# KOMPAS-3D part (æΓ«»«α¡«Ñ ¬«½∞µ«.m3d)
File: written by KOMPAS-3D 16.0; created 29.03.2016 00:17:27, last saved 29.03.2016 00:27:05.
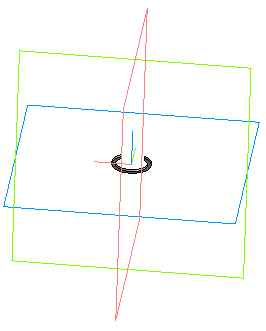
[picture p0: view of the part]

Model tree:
1. Эскиз:1
2. Операция выдавливания:1
     Расстояние 1 = 0.5; На расстояние 1 = 18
